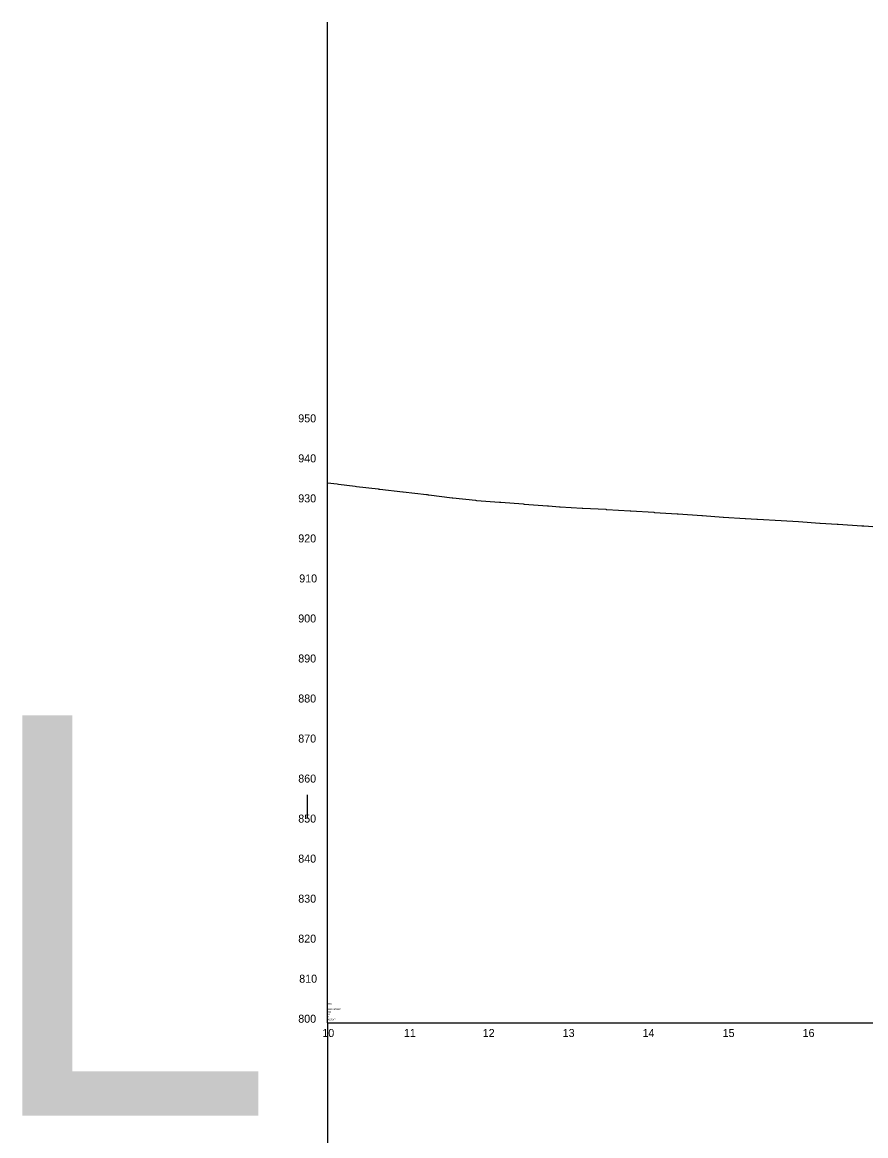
# Model space of a CAD drawing. Extents: x 1968019 to 1983409, y 545058 to 567558.
# Drawn here: x 1968462 to 1969515, y 566168 to 567558 of the extents above; entities that cross this region are included whole.
import ezdxf

# ---------------------------------------------------------------- set-up
doc = ezdxf.new("R2010")
doc.units = 0
for name, color, linetype in [('Default', 7, 'Continuous'), ('Exist Profile Cell', 7, 'Continuous'), ('Exist Vertical Profile Ground Line', 7, 'Continuous'), ('Exist Vertical Profile Horizontal Axis Label Major', 7, 'Continuous'), ('Exist Vertical Profile Vertical Axis Label', 7, 'Continuous'), ('Scratch_Level_1', 7, 'Continuous')]:
    doc.layers.add(name, color=color, linetype=linetype)

msp = doc.modelspace()

# ---------------------------------------------------------------- linework, layer by layer
at = {"layer": 'Exist Profile Cell'}
for q in [(1968843, 567558.4), (1972643, 566308.4), (1968843, 565058.4)]:
    msp.add_line((1968843, 566308.4), q, dxfattribs=at)
at = {"layer": 'Exist Vertical Profile Ground Line'}
msp.add_lwpolyline([(1968843, 566983.3), (1968855.2, 566981.7), (1968856.5, 566981.6), (1968877.7, 566978.9), (1968879, 566978.7), (1968906.2, 566975.5), (1968906.3, 566975.5), (1968907.2, 566975.4), (1968908.2, 566975.3), (1968937.2, 566971.9), (1968937.4, 566971.9), (1968937.4, 566971.9), (1968966.6, 566968.5), (1968967.4, 566968.4), (1968968.7, 566968.2), (1968968.8, 566968.2), (1968969.6, 566968.1), (1968998.7, 566964.5), (1968999.7, 566964.4), (1969027.8, 566961.3), (1969028, 566961.3), (1969029.1, 566961.2), (1969058, 566958.8), (1969058, 566958.8), (1969058.5, 566958.9), (1969059.6, 566958.8), (1969087.3, 566956.7), (1969087.3, 566956.7), (1969088.8, 566956.5), (1969118, 566954.3), (1969118.8, 566954.2), (1969119.2, 566954.2), (1969132.7, 566953.2), (1969133.5, 566953.2), (1969161.1, 566951.5), (1969162.1, 566951.4), (1969190.6, 566950.1), (1969191.2, 566950), (1969192, 566950), (1969221.2, 566948.1), (1969221.9, 566948.1), (1969250.5, 566946.3), (1969251.4, 566946.2), (1969280, 566944.3), (1969280, 566944.3), (1969280.6, 566944.3), (1969281.3, 566944.3), (1969310.6, 566942.2), (1969311.4, 566942.2), (1969337.2, 566940.3), (1969337.9, 566940.2), (1969364.8, 566938.7), (1969365.1, 566938.7), (1969379.6, 566937.9), (1969379.6, 566937.9), (1969379.7, 566937.9), (1969380.2, 566937.8), (1969409.7, 566936.1), (1969410, 566936.1), (1969431.3, 566934.7), (1969431.6, 566934.7), (1969458.3, 566932.8), (1969458.6, 566932.8), (1969479.9, 566931.5), (1969480.7, 566931.4), (1969481, 566931.4), (1969510.7, 566929.4), (1969511.5, 566929.4), (1969513, 566929.3), (1969541.5, 566927.5)], dxfattribs=at)
at = {"layer": 'Scratch_Level_1'}
msp.add_line((1968818, 566563.7), (1968818, 566593.5), dxfattribs=at)

# ---------------------------------------------------------------- texts
at = {"layer": 'Default'}
msp.add_text('L', height=500, dxfattribs=at).set_placement((1968406.7, 566192.5))
at = {"layer": 'Exist Profile Cell'}
for s, p in [('800', (1968843, 566321.4)), ('RDY', (1968843, 566331.2)), ('L', (1968843, 566327.9)), ('1000.000000', (1968843, 566324.7)), ('2', (1968843, 566314.9)), ('10', (1968843, 566318.2)), ('NOGAP', (1968843, 566311.7))]:
    msp.add_text(s, height=2, dxfattribs=at).set_placement(p)
at = {"layer": 'Exist Vertical Profile Horizontal Axis Label Major'}
for s, p in [('10', (1968836.5, 566290.9)), ('11', (1968938.4, 566290.9)), ('12', (1969036.9, 566290.9)), ('13', (1969136.8, 566290.9)), ('14', (1969236.6, 566290.9)), ('15', (1969336.7, 566290.9)), ('16', (1969436.6, 566290.9))]:
    msp.add_text(s, height=10, dxfattribs=at).set_placement(p)
at = {"layer": 'Exist Vertical Profile Vertical Axis Label'}
for s, p in [('950', (1968806.4, 567058.7)), ('940', (1968806.4, 567008.7)), ('930', (1968806.4, 566958.7)), ('920', (1968806.4, 566908.7)), ('910', (1968807.6, 566858.7)), ('900', (1968806.4, 566808.7)), ('890', (1968806.4, 566758.7)), ('880', (1968806.4, 566708.7)), ('870', (1968806.4, 566658.7)), ('860', (1968806.4, 566608.7)), ('850', (1968806.4, 566558.7)), ('840', (1968806.4, 566508.7)), ('830', (1968806.4, 566458.7)), ('820', (1968806.4, 566408.7)), ('810', (1968807.6, 566358.7)), ('800', (1968806.4, 566308.7))]:
    msp.add_text(s, height=10, dxfattribs=at).set_placement(p)

doc.saveas('drawing.dxf')
